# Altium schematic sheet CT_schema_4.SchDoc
size 255 x 245 mm
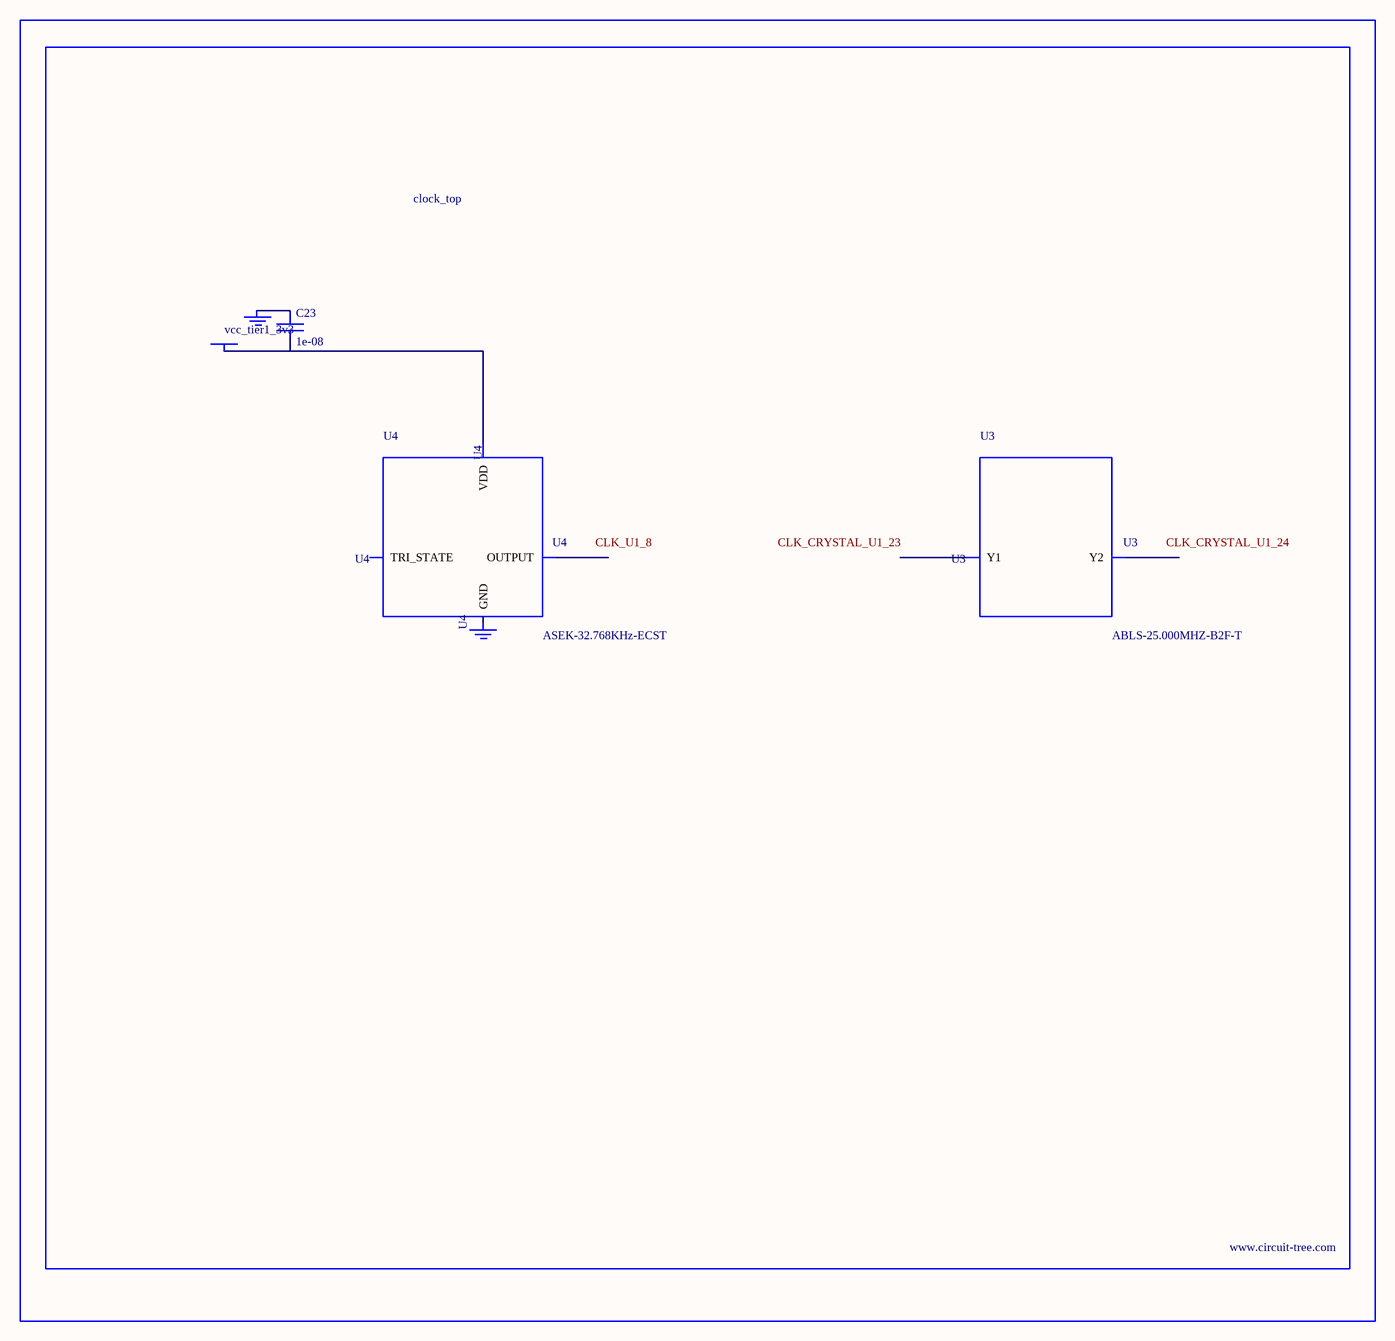
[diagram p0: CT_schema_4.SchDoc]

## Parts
BORDER3  (no value)
C23  1e-08  [C0402]
GND_INSTANCE_3_0  (no value)
GND_INSTANCE_3_1  (no value)
POWER_INSTANCE_3_0  vcc_tier1_3v3
U3  ABLS-25.000MHZ-B2F-T  [ABLS-25.000MHZ-B2F-T]
U4  ASEK-32.768KHz-ECST  [ASEK]

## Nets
NetC23_1: C23.1 GND_INSTANCE_3_0.0(GND)
NetC23_2: C23.2 POWER_INSTANCE_3_0.0(PWR) U4.4(VDD)

Not connected (* = marked no-connect by the designer): GND_INSTANCE_3_1 0(GND); U3 1(Y1) 2(Y2); U4 1(TRI_STATE) 2(GND) 3(OUTPUT)

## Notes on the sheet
- Labels drawn without touching a wire or pin: CLK_CRYSTAL_U1_23, CLK_CRYSTAL_U1_24, CLK_U1_8

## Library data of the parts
BORDER3 = BORDER_PAGE3
C23 = C0402C103K3RAC
GND_INSTANCE_3_0 GND_INSTANCE_3_1 = GND
POWER_INSTANCE_3_0 = PWR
